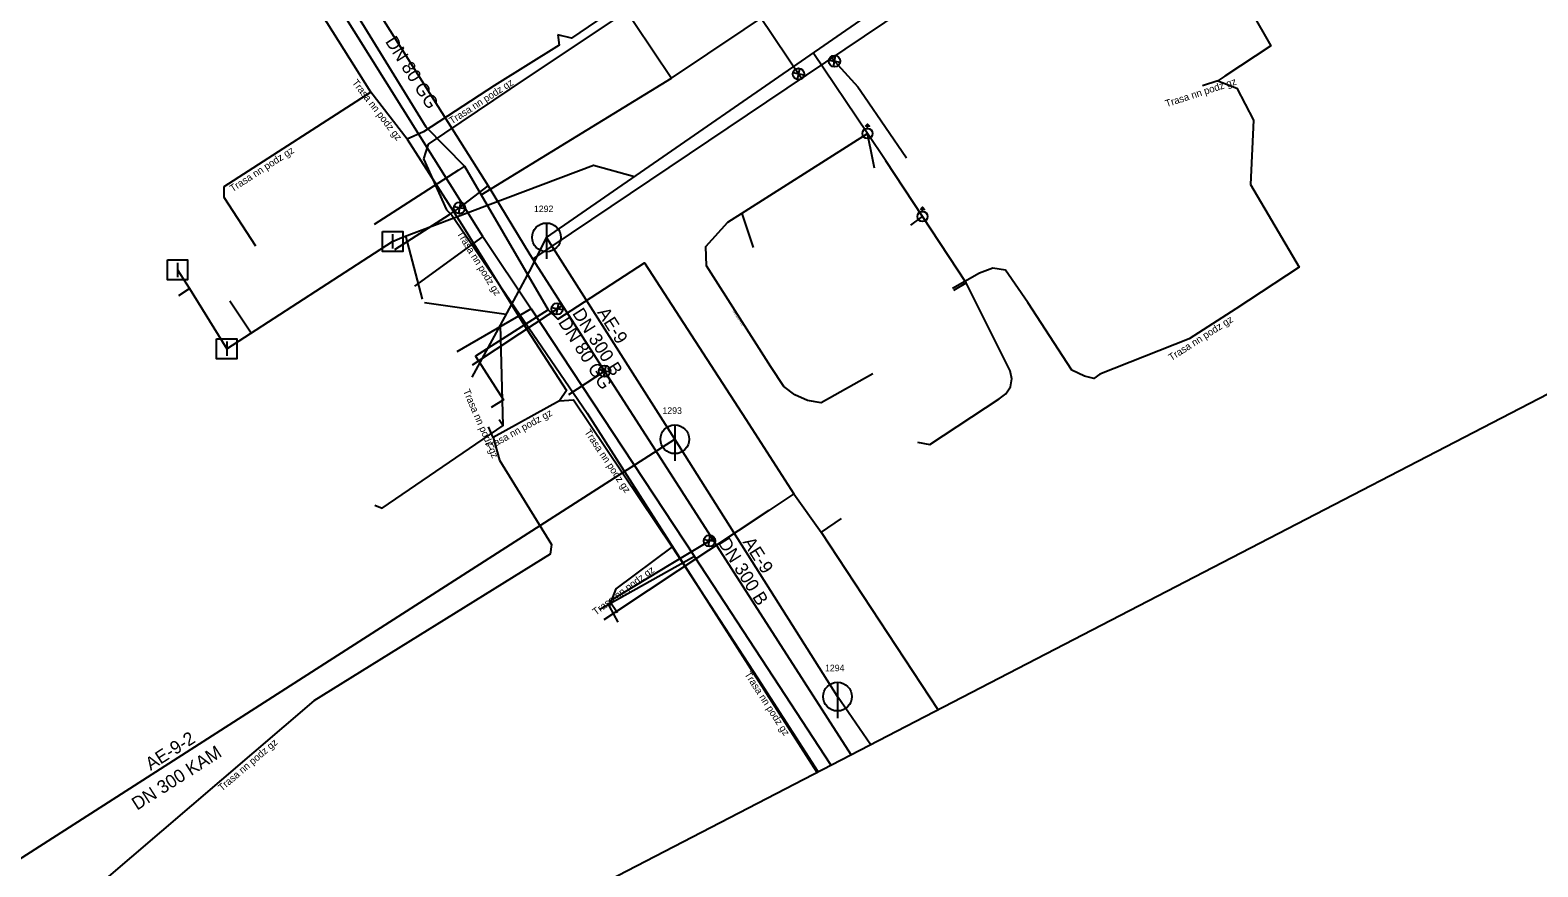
# Model space of a CAD drawing. Extents: x -493753 to -49291, y -1127285 to -112662.
# Drawn here: x -493093.4 to -492988.4, y -1127031.2 to -1126972.9 of the extents above; entities that cross this region are included whole.
import ezdxf

# ---------------------------------------------------------------- set-up
doc = ezdxf.new("R2010")
doc.units = 0
for name, color, linetype in [('Vrstva 1', 7, 'Continuous'), ('Vrstva 15', 7, 'Continuous'), ('Vrstva 17', 7, 'Continuous'), ('Vrstva 19', 7, 'Continuous'), ('Vrstva 20', 7, 'Continuous'), ('Vrstva 22', 7, 'Continuous'), ('Vrstva 24', 7, 'Continuous'), ('Vrstva 26', 7, 'Continuous'), ('Vrstva 39', 7, 'Continuous'), ('Vrstva 5', 7, 'Continuous'), ('Vrstva 9', 7, 'Continuous')]:
    doc.layers.add(name, color=color, linetype=linetype)

# ---------------------------------------------------------------- blocks, each defined once
blk = doc.blocks.new('_UZAV0')
at = {"layer": 'Vrstva 1'}
for p, q in [((-0.035, -0.035), (0.035, 0.035)), ((0.035, -0.035), (-0.035, 0.035))]:
    blk.add_line(p, q, dxfattribs=at)
for radius in [0.05, 0.0025]:
    blk.add_circle((0, 0), radius, dxfattribs=at)
blk = doc.blocks.new('_VPUST')
at = {"layer": 'Vrstva 1'}
blk.add_line((0, 0.025), (0, -0.025), dxfattribs=at)
blk.add_lwpolyline([(-0.035, 0.035), (0.035, 0.035), (0.035, -0.035), (-0.035, -0.035), (-0.035, 0.035)], dxfattribs=at)
blk = doc.blocks.new('_SACHT')
at = {"layer": 'Vrstva 1'}
blk.add_line((0, 0.035), (0, 0.05), dxfattribs=at)
blk.add_lwpolyline([(-0.015, 0.05), (0, 0.065), (0.015, 0.05), (0.0025, 0.05)], close=True, dxfattribs=at)
blk.add_circle((0, 0), 0.035, dxfattribs=at)
blk = doc.blocks.new('_SACH0')
at = {"layer": 'Vrstva 1'}
blk.add_line((0, 0.05), (0, -0.075), dxfattribs=at)
blk.add_circle((0, 0), 0.05, dxfattribs=at)

msp = doc.modelspace()

# ---------------------------------------------------------------- linework, layer by layer
at = {"layer": 'Vrstva 1'}
for p, q in [((-493052.53, -1126970.5), (-493048.7, -1126976.24)), ((-493068.1, -1126985.59), (-493069.41, -1126986.44)), ((-493040.17, -1127005.19), (-493041.92, -1127006.35)), ((-493041.92, -1127006.35), (-493052.46, -1127013.35)), ((-493036.88, -1127006.91), (-493038.27, -1127007.88)), ((-493052.46, -1127013.35), (-493053.41, -1127013.98))]:
    msp.add_line(p, q, dxfattribs=at)
for points in [[(-493753.13, -1126773.63), (-493540.88, -1127284.87), (-492737.61, -1126868.64), (-492950.39, -1126535.73)], [(-493061.95, -1126984.36), (-493055.3, -1126980.28), (-493048.7, -1126976.24), (-493041.12, -1126971.16), (-493033.53, -1126966.06), (-493026.17, -1126961.12), (-493022.95, -1126958.96), (-493022.37, -1126958.57), (-493017.3, -1126955.17), (-493012.3, -1126951.82), (-493006.38, -1126947.79), (-492996.36, -1126941.15), (-492992.52, -1126938.61), (-492984.26, -1126933.14), (-492976.86, -1126928.19), (-492969.03, -1126922.96), (-492962.21, -1126918.4), (-492958.1, -1126915.7), (-492957.92, -1126915.58), (-492957.82, -1126915.51), (-492938.13, -1126902.44)], [(-493075.92, -1126963.23), (-493074.66, -1126965.23), (-493065.8, -1126979.63), (-493063.11, -1126982.37), (-493061.95, -1126984.36), (-493057.28, -1126992.38), (-493056.62, -1126993.03), (-493050.57, -1126989.11), (-493043.53, -1127000), (-493040.17, -1127005.19), (-493038.27, -1127007.88), (-493030.16, -1127020.23)], [(-493063.11, -1126982.37), (-493063.53, -1126982.64), (-493068.1, -1126985.59)], [(-493057.28, -1126992.38), (-493062.34, -1126995.6), (-493060.4, -1126998.64), (-493061.25, -1126999.18)]]:
    msp.add_lwpolyline(points, dxfattribs=at)
at = {"layer": 'Vrstva 15'}
for p, q in [((-493057.41, -1126987.33), (-493004.52, -1126950.73)), ((-493035.05, -1126980.09), (-493038.83, -1126974.47)), ((-493034.69, -1126981.92), (-493035.05, -1126980.09)), ((-493034.57, -1126982.51), (-493034.69, -1126981.92)), ((-493042.98, -1126988.04), (-493043.79, -1126985.66)), ((-493032.03, -1126986.47), (-493031.22, -1126985.88)), ((-493079.68, -1126995.09), (-493068.12, -1126987.61)), ((-493066.04, -1126991.64), (-493067.21, -1126987.23)), ((-493048.47, -1127001.4), (-493057.41, -1126987.33)), ((-493083.11, -1126989.6), (-493082.27, -1126990.89)), ((-493029.03, -1126991.01), (-493028.17, -1126990.5)), ((-493083.02, -1126991.39), (-493082.27, -1126990.89)), ((-493082.27, -1126990.89), (-493079.68, -1126995.09)), ((-493079.45, -1126991.76), (-493077.98, -1126993.99)), ((-493065.9, -1126991.87), (-493060.21, -1126992.69)), ((-493062.59, -1126997.07), (-493060.62, -1126993.45)), ((-493060.71, -1127000.02), (-493060.43, -1127000.44)), ((-493116.77, -1127045.17), (-493048.47, -1127001.4)), ((-493037.14, -1127019.33), (-493048.47, -1127001.4)), ((-493034.85, -1127022.66), (-493037.14, -1127019.33))]:
    msp.add_line(p, q, dxfattribs=at)
for points in [[(-493034.68, -1126996.84), (-493038.28, -1126998.87), (-493039.22, -1126998.69), (-493040.1, -1126998.3), (-493040.87, -1126997.73), (-493041.79, -1126996.34), (-493046.26, -1126989.32), (-493046.32, -1126987.96), (-493044.77, -1126986.28), (-493035.05, -1126980.09)], [(-493031.22, -1126985.88), (-493033.78, -1126981.99), (-493035.05, -1126980.09)], [(-493068.12, -1126987.61), (-493067.49, -1126987.33), (-493054.13, -1126982.3), (-493051.28, -1126983.09)], [(-493031.56, -1127001.59), (-493030.7, -1127001.76), (-493025.87, -1126998.57), (-493025.41, -1126998.23), (-493025.1, -1126997.75), (-493025, -1126997.18), (-493025.11, -1126996.62), (-493028.17, -1126990.5), (-493031.22, -1126985.88)], [(-493060.62, -1126993.45), (-493058.43, -1126989.41), (-493057.41, -1126987.33)], [(-493069.36, -1127006), (-493068.86, -1127006.19), (-493060.43, -1127000.44), (-493060.62, -1126993.45)]]:
    msp.add_lwpolyline(points, dxfattribs=at)
at = {"layer": 'Vrstva 20'}
for p, q in [((-493039.64, -1126976.26), (-493046.48, -1126966.09)), ((-493035.26, -1126977.52), (-493032.34, -1126981.78)), ((-493067.96, -1126988.18), (-493064.17, -1126985.74)), ((-493058.56, -1126988.53), (-493058.35, -1126988.86)), ((-493058.35, -1126988.86), (-493058.17, -1126989.16)), ((-493059.26, -1126994.04), (-493056.26, -1126992.05)), ((-493062.55, -1126996.22), (-493059.26, -1126994.04)), ((-493055.84, -1126998.28), (-493053.36, -1126996.65)), ((-493052.9, -1127012.62), (-493048.72, -1127010.08))]:
    msp.add_line(p, q, dxfattribs=at)
for points in [[(-493058.35, -1126988.86), (-493024.34, -1126965.95), (-493020.92, -1126963.84), (-493020.12, -1126963.55), (-493013.01, -1126958.95), (-493005.99, -1126954.61), (-492997.24, -1126948.09), (-492993.15, -1126944.92), (-492989.76, -1126942.99), (-492970.31, -1126930.58), (-492962.98, -1126925.47), (-492940.62, -1126910.81)], [(-493073.46, -1126964.75), (-493072.94, -1126965.55), (-493061.46, -1126983.73), (-493058.56, -1126988.53)], [(-493037.5, -1126974.81), (-493037.35, -1126975.05), (-493035.73, -1126976.84), (-493035.26, -1126977.52)], [(-493064.17, -1126985.74), (-493063.46, -1126985.28), (-493061.46, -1126983.73)], [(-493058.17, -1126989.16), (-493053.36, -1126996.65), (-493049.64, -1127002.46)], [(-493049.64, -1127002.46), (-493036.22, -1127023.37)], [(-493048.72, -1127010.08), (-493046.06, -1127008.47), (-493045.85, -1127008.36)], [(-493052.46, -1127013.5), (-493053.04, -1127012.66), (-493052.9, -1127012.62)]]:
    msp.add_lwpolyline(points, dxfattribs=at)
at = {"layer": 'Vrstva 26'}
for p, q in [((-493051.68, -1126971.48), (-493058.82, -1126976.24)), ((-493058.82, -1126976.24), (-493065.64, -1126980.84)), ((-493065.64, -1126980.84), (-493065.97, -1126981.87)), ((-493065.97, -1126981.87), (-493064.38, -1126985.42)), ((-493064.38, -1126985.42), (-493064.01, -1126985.79)), ((-493064.01, -1126985.79), (-493054.57, -1126999.58)), ((-493054.57, -1126999.58), (-493038.57, -1127024.59))]:
    msp.add_line(p, q, dxfattribs=at)
at = {"layer": 'Vrstva 39'}
for points in [[(-493061.83, -1126987.26), (-493074.18, -1126967.53), (-493079.47, -1126970.79)], [(-493061.83, -1126987.26), (-493066.61, -1126990.73)], [(-493061.83, -1126987.26), (-493058.48, -1126992.32)], [(-493058.48, -1126992.32), (-493063.66, -1126995.31)], [(-493058.48, -1126992.32), (-493047.1, -1127009.56)], [(-493047.1, -1127009.56), (-493053.69, -1127013.26)], [(-493041.6, -1127017.98), (-493047.1, -1127009.56)], [(-493037.61, -1127024.09), (-493041.6, -1127017.98)]]:
    msp.add_lwpolyline(points, dxfattribs=at)
at = {"layer": 'Vrstva 5'}
for points in [[(-492996.03, -1126954.47), (-493000.14, -1126957.18), (-493005.36, -1126960.95), (-493010.42, -1126965.02), (-493010.98, -1126966.94), (-493006.97, -1126973.98), (-493010.17, -1126976.1), (-493010.66, -1126976.42)], [(-493035.84, -1126959.14), (-493037.99, -1126961.44), (-493039.81, -1126962.4), (-493042.17, -1126964.29), (-493047.62, -1126967.95), (-493055.67, -1126973.45), (-493056.61, -1126973.22)], [(-493069.65, -1126977.21), (-493077.59, -1126964.57), (-493077.98, -1126964.63), (-493082.28, -1126966.46), (-493086.36, -1126968.91), (-493086.27, -1126969.46)], [(-493056.61, -1126973.22), (-493056.53, -1126973.95), (-493061.02, -1126976.76), (-493065.98, -1126979.97), (-493067.11, -1126980.49)], [(-493010.66, -1126976.42), (-493009.32, -1126976.93), (-493008.16, -1126979.17), (-493008.38, -1126983.64), (-493004.99, -1126989.41), (-493009.39, -1126992.31), (-493012.64, -1126994.39), (-493018.87, -1126996.86), (-493019.29, -1126997.16), (-493019.94, -1126996.99), (-493020.81, -1126996.58), (-493023.89, -1126991.86), (-493025.44, -1126989.61), (-493026.32, -1126989.48), (-493027.25, -1126989.82), (-493029.12, -1126990.89)], [(-493010.66, -1126976.42), (-493011.72, -1126976.77)], [(-493069.65, -1126977.21), (-493079.88, -1126983.81), (-493079.88, -1126984.53), (-493077.67, -1126987.93)], [(-493067.11, -1126980.49), (-493069.65, -1126977.21)], [(-493067.11, -1126980.49), (-493063.31, -1126986.44), (-493058.76, -1126993.78), (-493056.01, -1126998), (-493056.49, -1126998.71)], [(-493056.49, -1126998.71), (-493061.12, -1127001.27)], [(-493056.49, -1126998.71), (-493055.52, -1126998.65), (-493048.65, -1127008.89)], [(-493061.12, -1127001.27), (-493060.67, -1127002.85), (-493057.06, -1127008.73), (-493057.15, -1127009.4), (-493073.62, -1127019.63), (-493096.95, -1127039.58), (-493101.46, -1127043), (-493102.72, -1127044.05), (-493103.35, -1127045.66)], [(-493061.12, -1127001.27), (-493061.44, -1127000.52)], [(-493048.65, -1127008.89), (-493052.57, -1127011.83), (-493053.04, -1127013.02), (-493052.43, -1127014.14)], [(-493048.65, -1127008.89), (-493042.7, -1127018.02), (-493038.51, -1127024.55)]]:
    msp.add_lwpolyline(points, dxfattribs=at)

# ---------------------------------------------------------------- block references
at = {"layer": 'Vrstva 17'}
for name, p, xscale, yscale in [('_SACHT', (-493035.05, -1126980.09), 9.998750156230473, 9.998750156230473), ('_SACHT', (-493031.22, -1126985.88), 9.998750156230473, 9.998750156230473), ('_SACH0', (-493057.41, -1126987.33), 19.997500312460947, 19.997500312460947), ('_VPUST', (-493068.12, -1126987.61), 19.997500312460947, 19.997500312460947), ('_VPUST', (-493083.11, -1126989.6), 19.997500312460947, 19.997500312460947), ('_VPUST', (-493079.68, -1126995.09), 19.997500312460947, 19.997500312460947), ('_SACH0', (-493048.47, -1127001.4), 19.997500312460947, 19.997500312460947), ('_SACH0', (-493037.14, -1127019.33), 19.997500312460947, 19.997500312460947)]:
    msp.add_blockref(name, p, dxfattribs=dict(at, xscale=xscale, yscale=yscale))
at = {"layer": 'Vrstva 22'}
for p, xscale, yscale, rotation in [((-493037.35, -1126975.05), 7.999000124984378, 7.999000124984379, -55.534663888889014), ((-493039.85, -1126975.95), 7.999000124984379, 7.999000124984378, 33.9172388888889), ((-493063.46, -1126985.28), 7.999000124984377, 7.999000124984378, 124.36863888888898), ((-493056.66, -1126992.31), 7.999000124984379, 7.999000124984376, 123.578327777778), ((-493053.36, -1126996.65), 7.999000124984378, 7.999000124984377, 123.382236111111), ((-493046.06, -1127008.47), 7.999000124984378, 7.999000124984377, 36.58975833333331)]:
    msp.add_blockref('_UZAV0', p, dxfattribs=dict(at, xscale=xscale, yscale=yscale, rotation=rotation))

# ---------------------------------------------------------------- texts
at = {"layer": 'Vrstva 19'}
for s, p in [('1292', (-493058.28, -1126985.57)), ('1293', (-493049.33, -1126999.63)), ('1294', (-493038.01, -1127017.56))]:
    msp.add_text(s, height=0.455, dxfattribs=at).set_placement(p)
for s, height, rotation, p in [('DN 300 B', 0.91, 302.4564, (-493055.64, -1126992.62)), ('AE-9', 0.91, 302.4564, (-493053.91, -1126992.56)), ('DN 150 PVC', 0.16, 302.4657, (-493044.45, -1126992.46)), ('DN 300 B', 0.91, 302.2708, (-493045.49, -1127008.61)), ('AE-9', 0.91, 302.2708, (-493043.77, -1127008.56)), ('AE-9-2', 0.91, 32.6565, (-493084.97, -1127024.51)), ('DN 300 KAM', 0.91, 32.6565, (-493085.92, -1127027.28))]:
    msp.add_text(s, height=height, rotation=rotation, dxfattribs=at).set_placement(p)
at = {"layer": 'Vrstva 24'}
for rotation, p in [(302.287, (-493068.67, -1126973.68)), (302.6834, (-493056.62, -1126993.25))]:
    msp.add_text('DN 80 GG', height=0.91, rotation=rotation, dxfattribs=at).set_placement(p)
at = {"layer": 'Vrstva 9'}
for rotation, p in [(307.7743, (-493070.98, -1126976.56)), (32.91, (-493063.99, -1126979.47)), (18.0934, (-493014.22, -1126978.27)), (32.8467, (-493079.27, -1126984.19)), (301.7598, (-493063.68, -1126987.06)), (32.6603, (-493013.89, -1126995.96)), (293.459, (-493063.23, -1126998.03)), (28.9062, (-493061.47, -1127002.2)), (303.8151, (-493054.79, -1127000.9)), (36.809, (-493053.97, -1127013.69)), (302.7352, (-493043.64, -1127017.77)), (40.5371, (-493080.01, -1127025.95))]:
    msp.add_text('Trasa nn podz gz', height=0.5, rotation=rotation, dxfattribs=at).set_placement(p)

doc.saveas('drawing.dxf')
